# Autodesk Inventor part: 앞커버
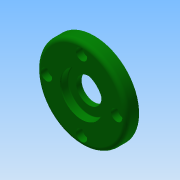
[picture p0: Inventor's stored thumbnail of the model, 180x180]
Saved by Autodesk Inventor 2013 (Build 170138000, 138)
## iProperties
Created: 2019-01
Part Number: 앞커버
Material: 알루미늄 6061
Document SubType Name: Modeling
Designer: mduedu
Density: 2.71 g/cm^3
Mass: 66.3541 g
Surface Area: 91.8017 cm^2
Volume: 24.4849 cm^3
Author: mduedu
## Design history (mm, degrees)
sketch "스케치1"
  geometry: L1 (0, 0)-(9, 0); L2 (9, 0)-(9, 32); L3 (9, 32)-(0, 32); L4 (0, 32)-(0, 0); L5 (9, 0)-(12, 0); L6 (12, 0)-(12, 20); L7 (12, 20)-(9, 20); L8 (9, 20)-(9, 0)
  constraints: 16 end point, 4 parallel, 2 horizontal, 2 perpendicular
  dimensions: "d0" = 12 distance between parallel lines of L6 L4; "d2" = 64 diameter of L3 L1; "d3" = 40 diameter of L7 L5; "d4" = 3 distance between parallel lines of L6 L2
revolve "회전1" sketch "스케치1" stored, may be unused: angle "d5" = 90 deg
sketch "스케치2"
  geometry: L1 (0, -32)-(0, 32) reference; L2 (0, 32)-(9, 32) reference; L3 (9, 32)-(9, 20) reference; L4 (9, 20)-(12, 20) reference; L5 (12, 20)-(12, -20) reference; L6 (12, -20)-(9, -20) reference; L7 (9, -20)-(9, -32) reference; L8 (9, -32)-(0, -32) reference; L9 (0, 0)-(5.2, 0); L10 (5.2, 0)-(5.2, 15); L11 (5.2, 15)-(0, 15); L12 (0, 15)-(0, 0); L13 (5.2, 0)-(9, 0); L14 (9, 0)-(9, 9); L15 (9, 9)-(5.2, 9); L16 (5.2, 9)-(5.2, 0); L17 (9, 0)-(12, 0); L18 (12, 0)-(12, 15); L19 (12, 15)-(9, 15); L20 (9, 15)-(9, 0)
  constraints: 24 end point, 6 parallel, 3 horizontal, 3 perpendicular, 1 point on line
  dimensions: "d6" = 3 distance of L18.end L19.end; "d8" = 5.2 distance of L10.end L11.end; "d9" = 30 diameter of L11 L9; "d10" = 18 diameter of L15 L13; "d11" = 30 diameter of L19 L17
revolve "회전2" sketch "스케치2" stored, may be unused: angle "d12" = 90 deg
chamfer "모따기1" distance "d13" = 0.5; stored, may be unused: second distance "d14" = 2, angle "d15" = 30 deg
fillet "모깎기1" dims "d16" = 0.5
fillet "모깎기2" dims "d17" = 3
fillet "모깎기3" dims "d18" = 3
chamfer "모따기2" distance "d24" = 1; stored, may be unused: second distance "d25" = 2, angle "d26" = 45 deg
sketch "스케치3" dims "d19" = 50
  geometry: 6 further points
  constraints: 2 vertical alignment, 1 coincident, 7 other
  dimensions: "d22" = 360 deg dimension on point (0, 0) point (0, 25) (derived)
sketch "스케치4"
  geometry: 4 further points
  constraints: 4 other
hole "구멍1" sketch "스케치4" at (-25, 0), (0, -25), (25, 0), (0, 25) diameter "d27" = 4.5; stored, may be unused: countersink angle "d31" = 90 deg, drill point angle "d33" = 0 deg; dims "d28" = 6, "d29" = 8, "d30" = 4.6, "d32" = 8
node "솔리드1"
node "절단 모서리 투영1"
